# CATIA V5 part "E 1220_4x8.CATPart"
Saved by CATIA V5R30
Part number: Sroub_M4x8_1
Definition: E 1220_4x8
Nomenclature: E 1220_4x8
Source: Unknown
Description: PART--DESC
Bounding box of the stored display mesh (mm): x -6.429 to 2.991, y -9.663 to -1.444, z 8 to 16
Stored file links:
  E:\Bakalarka\Model\Forma_v7\E 1220_4x8.CATPart
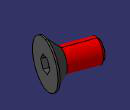
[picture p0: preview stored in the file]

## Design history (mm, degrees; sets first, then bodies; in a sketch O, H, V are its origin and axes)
Body1 "MANIFOLD_SOLID_BREP #213" (main body)
  Solid1: solid without history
